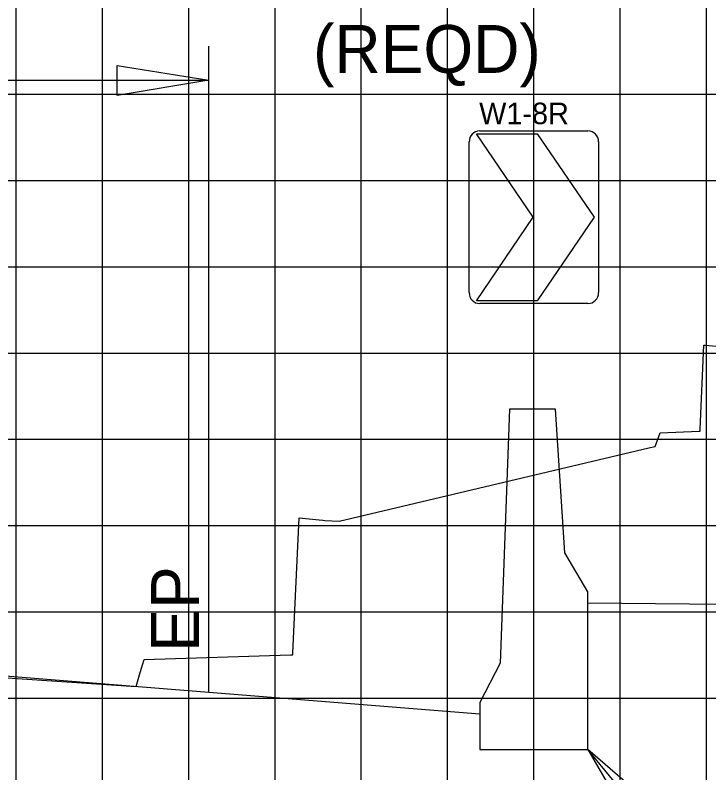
# Model space of a CAD drawing. Extents: x 2193008 to 2198143, y 1236112 to 1237864.
# Drawn here: x 2195376.61 to 2195392.69, y 1237268.37 to 1237285.94 of the extents above; entities that cross this region are included whole.
import ezdxf

# ---------------------------------------------------------------- set-up
doc = ezdxf.new("R2010")
doc.units = 0
for name, color, linetype in [('3', 7, 'Continuous'), ('CL-CNST', 7, 'Continuous'), ('GSDIMS', 7, 'Continuous'), ('Level 1', 7, 'Continuous'), ('Level 55', 7, 'Continuous'), ('Level 62', 7, 'Continuous'), ('M-ROADS', 7, 'Continuous')]:
    doc.layers.add(name, color=color, linetype=linetype)

msp = doc.modelspace()

# ---------------------------------------------------------------- linework, layer by layer
msp.add_lwpolyline([(2195389.882, 1237272.567), (2195389.353, 1237273.477), (2195389.131, 1237276.807), (2195388.068, 1237276.807), (2195387.852, 1237270.914), (2195387.382, 1237270.004), (2195387.382, 1237268.914), (2195389.882, 1237268.914)], close=True)
at = {"layer": '3'}
for p, q in [((2195381.096, 1237270.247), (2195381.096, 1237285.215)), ((2195392.655, 1237265.565), (2195389.882, 1237268.914))]:
    msp.add_line(p, q, dxfattribs=at)
at = {"layer": 'CL-CNST'}
for points in [[(2195353.64, 1237272.272), (2195353.643, 1237272.341), (2195355.092, 1237272.327), (2195368.094, 1237271.287), (2195381.096, 1237270.247), (2195387.382, 1237269.744)], [(2195389.882, 1237272.317), (2195396.169, 1237272.254), (2195409.171, 1237271.214), (2195422.259, 1237270.167)]]:
    msp.add_lwpolyline(points, dxfattribs=at)
at = {"layer": 'GSDIMS'}
for p, q in [((2195368.094, 1237284.427), (2195381.097, 1237284.427)), ((2195388.632, 1237276.807), (2195388.632, 1237279.254))]:
    msp.add_line(p, q, dxfattribs=at)
for points in [[(2195381.097, 1237284.427), (2195378.968, 1237284.079), (2195378.968, 1237284.774)], [(2195389.882, 1237268.914), (2195390.959, 1237267.063), (2195391.49, 1237267.522)]]:
    msp.add_lwpolyline(points, close=True, dxfattribs=at)
at = {"layer": 'Level 1'}
for p, q in [((2195387.379, 1237283.254), (2195389.885, 1237283.254)), ((2195387.299, 1237283.19), (2195388.711, 1237283.19)), ((2195388.615, 1237281.254), (2195387.299, 1237283.19)), ((2195388.711, 1237283.19), (2195390.027, 1237281.254)), ((2195387.132, 1237279.508), (2195387.132, 1237282.999)), ((2195390.132, 1237282.999), (2195390.132, 1237279.508)), ((2195387.299, 1237279.318), (2195388.615, 1237281.254)), ((2195390.027, 1237281.254), (2195388.711, 1237279.318)), ((2195388.711, 1237279.318), (2195387.299, 1237279.318)), ((2195389.885, 1237279.254), (2195387.379, 1237279.254))]:
    msp.add_line(p, q, dxfattribs=at)
for centre, major_axis, start_param, end_param in [((2195387.379, 1237282.999), (0, 0.255), 0, 1.570796), ((2195389.885, 1237282.999), (0, 0.255), 4.712389, 6.283185), ((2195387.379, 1237279.508), (0, -0.255), 4.712389, 6.283185), ((2195389.885, 1237279.508), (0, 0.255), 3.141593, 4.712389)]:
    msp.add_ellipse(centre, major_axis=major_axis, ratio=0.970588, start_param=start_param, end_param=end_param, dxfattribs=at)
at = {"layer": 'Level 62'}
for p, q in [((2195376.632, 1237258.106), (2195376.632, 1237318.106)), ((2195378.632, 1237258.106), (2195378.632, 1237318.106)), ((2195380.632, 1237258.106), (2195380.632, 1237318.106)), ((2195382.632, 1237258.106), (2195382.632, 1237318.106)), ((2195384.632, 1237258.106), (2195384.632, 1237318.106)), ((2195386.632, 1237258.106), (2195386.632, 1237318.106)), ((2195388.632, 1237258.106), (2195388.632, 1237318.106)), ((2195390.632, 1237258.106), (2195390.632, 1237318.106)), ((2195392.632, 1237258.106), (2195392.632, 1237318.106)), ((2195328.632, 1237284.106), (2195448.632, 1237284.106)), ((2195328.632, 1237282.106), (2195448.632, 1237282.106)), ((2195328.632, 1237280.106), (2195448.632, 1237280.106)), ((2195328.632, 1237278.106), (2195448.632, 1237278.106)), ((2195328.632, 1237276.106), (2195448.632, 1237276.106)), ((2195328.632, 1237274.106), (2195448.632, 1237274.106)), ((2195328.632, 1237272.106), (2195448.632, 1237272.106)), ((2195328.632, 1237270.106), (2195448.632, 1237270.106))]:
    msp.add_line(p, q, dxfattribs=at)
at = {"layer": 'M-ROADS'}
msp.add_lwpolyline([(2195370.209, 1237270.993), (2195379.415, 1237270.375), (2195379.505, 1237270.698), (2195379.598, 1237271.002), (2195382.993, 1237271.11), (2195383.045, 1237271.112), (2195383.047, 1237271.159), (2195383.188, 1237274.282), (2195383.658, 1237274.239), (2195383.74, 1237274.228), (2195383.788, 1237274.226), (2195384.116, 1237274.208), (2195391.296, 1237275.905), (2195391.444, 1237275.94), (2195391.558, 1237276.252), (2195391.561, 1237276.259), (2195392.466, 1237276.295), (2195392.485, 1237276.296), (2195392.487, 1237276.337), (2195392.571, 1237278.289), (2195392.584, 1237278.288), (2195392.603, 1237278.286), (2195392.945, 1237278.255)], dxfattribs=at)

# ---------------------------------------------------------------- texts
at = {"layer": 'Level 1'}
msp.add_text('W1-8R', height=0.5, rotation=360, dxfattribs=at).set_placement((2195387.364, 1237283.41))
at = {"layer": 'Level 55'}
msp.add_text('(REQD)', height=1.1105, dxfattribs=at).set_placement((2195383.514, 1237284.599))
msp.add_text('EP', height=1.1105, rotation=90, dxfattribs=at).set_placement((2195380.869, 1237271.181))

doc.saveas('drawing.dxf')
